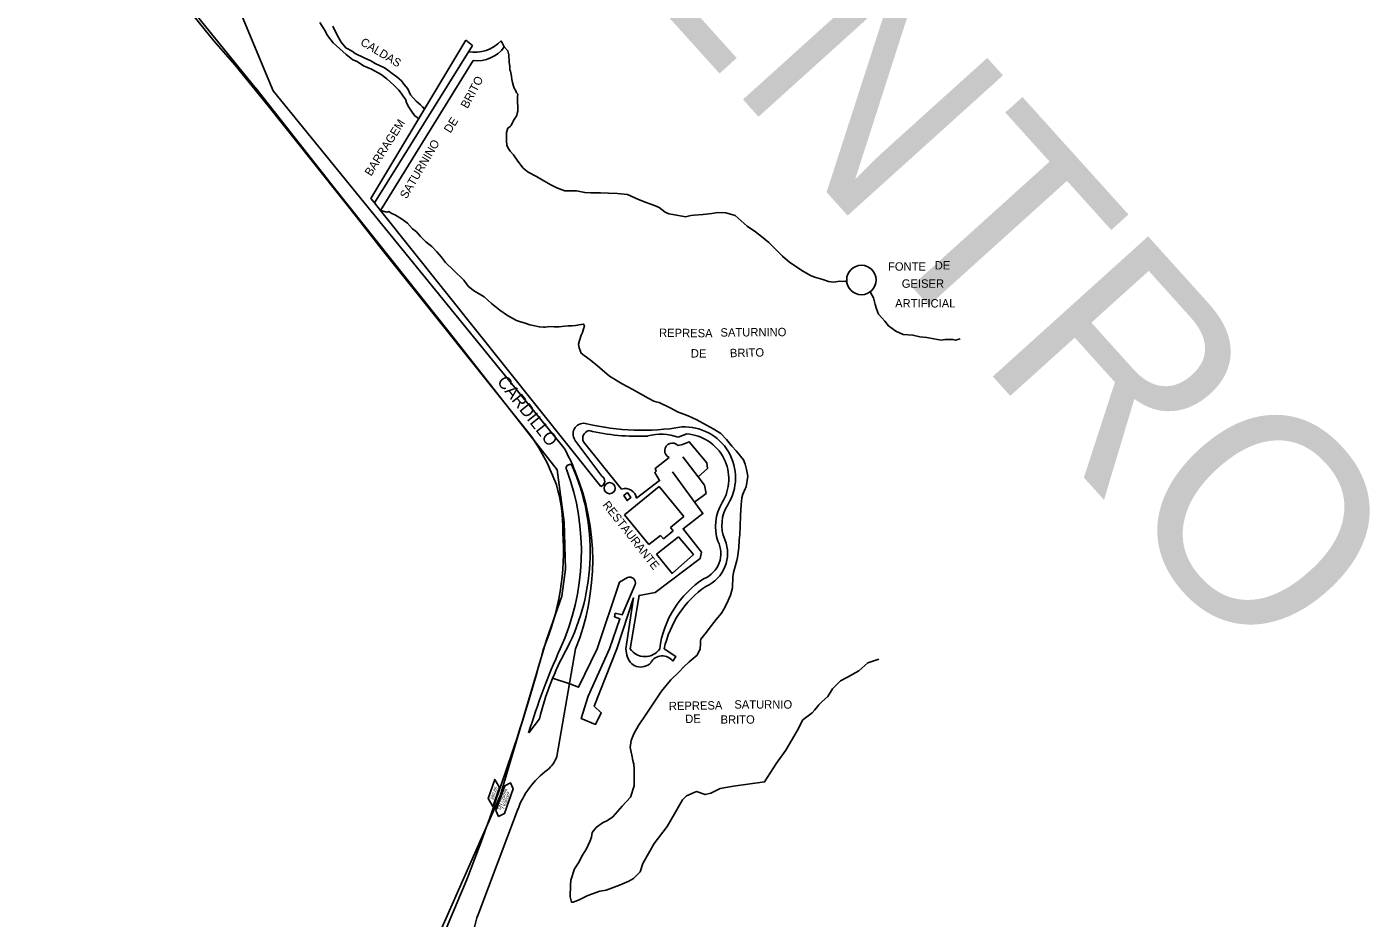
# Model space of a CAD drawing. Extents: x 325709 to 364434, y 7573432 to 7597073.
# Drawn here: x 339628 to 340271, y 7586373 to 7586799 of the extents above; entities that cross this region are included whole.
import ezdxf

# ---------------------------------------------------------------- set-up
doc = ezdxf.new("R2010")
doc.units = 0
for name, color, linetype in [('EDIFEXISTENT', 7, 'Continuous'), ('EDIFIDENTIF', 7, 'Continuous'), ('EDIFOBRAEXIS', 7, 'Continuous'), ('LIMITE_BAIRROS_MUNICIPIOS', 7, 'Continuous'), ('LOGRADOURO', 7, 'Continuous'), ('LOGRADOURO_TEXTO', 7, 'Continuous'), ('SIMBOLO', 7, 'Continuous'), ('TEXTO', 7, 'Continuous'), ('TUBO_PEAD_GN_125', 7, 'Continuous')]:
    doc.layers.add(name, color=color, linetype=linetype)

msp = doc.modelspace()

# ---------------------------------------------------------------- linework, layer by layer
at = {"layer": 'EDIFEXISTENT'}
for p, q in [((339792.51, 7586717.06), (339837.9, 7586792.71)), ((339840.97, 7586790.2), (339794.15, 7586714.93)), ((339837.9, 7586792.71), (339837.9, 7586792.71)), ((339837.9, 7586792.71), (339837.9, 7586792.71)), ((339837.9, 7586792.71), (339840.97, 7586790.2)), ((339854.7, 7586792.37), (339856.25, 7586789.42)), ((339841.37, 7586782.96), (339797.06, 7586711.32)), ((339792.51, 7586717.06), (339792.51, 7586717.06)), ((339794.15, 7586714.93), (339792.51, 7586717.06)), ((339797.06, 7586711.32), (339794.15, 7586714.93)), ((339913.76, 7586565.82), (339930.31, 7586579.38)), ((339930.31, 7586579.38), (339942.06, 7586565.04)), ((339925.28, 7586551.76), (339913.76, 7586565.82)), ((339942.06, 7586565.04), (339935.69, 7586559.82)), ((339930.97, 7586556.06), (339925.28, 7586551.76)), ((339932.34, 7586554.38), (339930.97, 7586556.06)), ((339937.01, 7586558.21), (339932.34, 7586554.38)), ((339935.69, 7586559.82), (339937.01, 7586558.21))]:
    msp.add_line(p, q, dxfattribs=at)
msp.add_circle((340026.92, 7586678.11), 7.03, dxfattribs=at)
for centre, radius, start, end in [((339841.76, 7586804.8), 17.94, 261.22228, 316.13289), ((339843.33, 7586798.82), 15.98, 262.9776, 323.96314)]:
    msp.add_arc(centre, radius, start, end, dxfattribs=at)
at = {"layer": 'EDIFOBRAEXIS'}
for p, q in [((339797.06, 7586711.32), (339902.34, 7586579.4)), ((339889.99, 7586601.64), (339902.86, 7586584.37)), ((339939.42, 7586602.99), (339943.53, 7586604.56)), ((339912.29, 7586578.21), (339894.07, 7586600.75)), ((339902.34, 7586579.4), (339902.34, 7586579.4)), ((339928.99, 7586547.03), (339939.46, 7586555.39)), ((339914.39, 7586501.91), (339914.87, 7586498.83)), ((339867.89, 7586461.75), (339873.07, 7586468.35))]:
    msp.add_line(p, q, dxfattribs=at)
for points in [[(339768.08, 7586801.11), (339770.27, 7586797.65), (339771.8, 7586794.9), (339774.4, 7586791.34), (339780.69, 7586785.81), (339783.78, 7586783.3), (339785.86, 7586782.55), (339789.02, 7586780.35), (339792.73, 7586778.81), (339797.37, 7586776.35), (339800.15, 7586774.19), (339803.45, 7586771.23), (339805.76, 7586768.73), (339806.9, 7586767.32), (339808.2, 7586765.42), (339808.98, 7586764.41), (339809.73, 7586762.37), (339810.6, 7586760.68), (339812.19, 7586758.2), (339813.46, 7586756.52), (339814.62, 7586755.65), (339815.32, 7586755.1)], [(339818.03, 7586759.75), (339817.17, 7586760.75), (339816.22, 7586761.77), (339814.1, 7586763.51), (339811.38, 7586766.59), (339810.85, 7586767.95), (339810.19, 7586769.44), (339808.27, 7586771.69), (339807.07, 7586773.3), (339804.86, 7586775.11), (339802.72, 7586776.8), (339800.64, 7586778.31), (339799.02, 7586779.4), (339794.46, 7586781.46), (339792.38, 7586782.82), (339789.31, 7586784.21), (339784.95, 7586786.27), (339783.59, 7586787.36), (339780.46, 7586788.98), (339778.3, 7586791.72), (339776.31, 7586795.14), (339774.36, 7586799.34)], [(339856.25, 7586789.42), (339858.01, 7586787.6), (339858.47, 7586785.62), (339858.51, 7586782.17), (339858.82, 7586780.14), (339858.95, 7586778.55), (339859.22, 7586777.87), (339859.67, 7586775.51), (339859.85, 7586773.81), (339860.1, 7586772.47), (339860.59, 7586770.75), (339861.01, 7586769.69), (339861.69, 7586768.41), (339862.14, 7586767.58), (339862.71, 7586766.95), (339862.53, 7586765.83), (339862.6, 7586763.34), (339862.67, 7586760.65), (339862.7, 7586758.77), (339862.42, 7586757.65), (339862.31, 7586756.71), (339860.67, 7586754.29), (339859.59, 7586751.96), (339859.04, 7586751.45), (339857.97, 7586750.56), (339857.27, 7586748.54), (339857.35, 7586746.79), (339857.23, 7586744.61), (339857.47, 7586742.5), (339858.08, 7586741.04), (339859, 7586739.63), (339860.63, 7586737.83), (339862.71, 7586734.8), (339865.26, 7586731.59), (339867.58, 7586729.55), (339871.6, 7586727.59), (339875.17, 7586725.46), (339878.48, 7586723.57), (339881.33, 7586722.14), (339885.16, 7586720.66), (339888.13, 7586720.66), (339890.83, 7586720.66), (339894.7, 7586719.84), (339897.57, 7586719.81), (339902.3, 7586719.66), (339906.09, 7586719.53), (339910.3, 7586719.4), (339915.06, 7586718.87), (339920.36, 7586716.55), (339924, 7586715.09), (339925.86, 7586714.41), (339928.11, 7586713.61), (339930.23, 7586712.76), (339933.12, 7586710.55), (339934.83, 7586709.74), (339938.63, 7586709.05), (339942.78, 7586708.31), (339945.44, 7586708.89), (339947.06, 7586709.04), (339951.22, 7586709.42), (339955.4, 7586709.9), (339958.24, 7586710.31), (339962.05, 7586710.19), (339966.57, 7586708.83), (339972.4, 7586703.82), (339976.36, 7586701.15), (339979.14, 7586698.94), (339982.7, 7586695.98), (339989.19, 7586689.41), (339992.64, 7586686.5), (339999.2, 7586682.07), (340002.89, 7586680.12), (340005.19, 7586679.35), (340008.41, 7586678.31), (340011.19, 7586677.4), (340013.77, 7586677.06), (340016.63, 7586677.47), (340018.05, 7586677.44), (340019.12, 7586677.46), (340020.07, 7586676.99)], [(339797.06, 7586711.32), (339800.17, 7586710.49), (339801, 7586710.81), (339802.21, 7586710.01), (339804.29, 7586709.14), (339807.19, 7586707.36), (339809.99, 7586705.22), (339812.4, 7586702.57), (339814.28, 7586701.08), (339816.17, 7586698.85), (339818.78, 7586696.36), (339821.67, 7586694.15), (339823.95, 7586691.6), (339826.2, 7586689.07), (339828.1, 7586686.44), (339832.03, 7586682.77), (339836.89, 7586678.01), (339839.04, 7586675.15), (339841.49, 7586673.06), (339846.62, 7586670.12), (339850.06, 7586666.81), (339854.15, 7586663.73), (339857.81, 7586661.13), (339862.12, 7586658.66), (339863.47, 7586658.2), (339866.23, 7586657.41), (339868.45, 7586656.74), (339869.98, 7586656.39), (339873.06, 7586655.7), (339874.95, 7586655.51), (339875.71, 7586655.62), (339877.99, 7586655.81), (339880.15, 7586655.65), (339882.39, 7586655.74), (339883.73, 7586655.91), (339885.15, 7586656.09), (339886.82, 7586656.15), (339888.47, 7586656.25), (339890.25, 7586656.33), (339891.26, 7586656.43), (339891.9, 7586656.64), (339893.01, 7586656.86), (339893.97, 7586657.03), (339894.2, 7586656.78), (339894.5, 7586655.85), (339894.23, 7586655.26), (339893.56, 7586653.01), (339893.05, 7586651.68), (339892.18, 7586649.15), (339891.75, 7586647.44), (339892.09, 7586645.62), (339892.94, 7586643.12), (339894.46, 7586642.08), (339897.24, 7586639.97), (339901.83, 7586636.11), (339906.55, 7586632.13), (339912.61, 7586628.48), (339917.4, 7586625.97), (339921.38, 7586623.73), (339925.02, 7586621.56), (339927.74, 7586620.23), (339928.86, 7586619.95), (339930.31, 7586619.59), (339935.82, 7586616.85), (339939.08, 7586615.07), (339944.12, 7586613.26), (339948.24, 7586611.35), (339952.86, 7586608.79), (339956.32, 7586606.87), (339959.66, 7586604.74), (339962.45, 7586601.89), (339964.97, 7586598.74), (339967.07, 7586596.39), (339970.57, 7586592.21), (339971.4, 7586590.04), (339971.97, 7586587.61), (339972.59, 7586584.32), (339971.79, 7586579.27), (339971.35, 7586578.33), (339970.3, 7586575.77), (339969.85, 7586573.96), (339969.4, 7586570.67), (339969.1, 7586565.79), (339968.99, 7586560.33), (339968.86, 7586556.54), (339968.57, 7586553.84), (339968.31, 7586550.05), (339967.68, 7586545.47), (339967.32, 7586544.09), (339965.77, 7586538.37), (339965.4, 7586536.26), (339965.27, 7586530.97), (339964.39, 7586527.5), (339962.58, 7586523.48), (339961.2, 7586520.87), (339960.04, 7586518.94), (339957.58, 7586515.85), (339954.2, 7586511.6), (339952.88, 7586509.88), (339951.52, 7586508.1), (339950.25, 7586506.56), (339950.02, 7586505.46), (339950.06, 7586504.29), (339949.78, 7586501.91)], [(340031.09, 7586672.51), (340032.72, 7586669.57), (340033.56, 7586666.44), (340034.16, 7586664.26), (340035.16, 7586661.84), (340036.62, 7586660.06), (340038.09, 7586658.49), (340039.94, 7586656.11), (340043.41, 7586653.58), (340046.87, 7586652.06), (340051.57, 7586651.79), (340054.86, 7586650.93), (340058.15, 7586650.61), (340061.56, 7586649.91), (340065, 7586649.38), (340067, 7586649.6), (340069.42, 7586649.64), (340070.66, 7586649.66), (340071.93, 7586649.4), (340074.11, 7586650)], [(339948.9, 7586583.98), (339953.3, 7586587.99), (339953.05, 7586590.68), (339944.59, 7586600.77), (339941.41, 7586599.54), (339939.29, 7586598.97)], [(339934.97, 7586593.23), (339928.4, 7586588.04), (339928.88, 7586586.78), (339928.13, 7586586.08), (339930.43, 7586582.28), (339919.43, 7586573.84)], [(339947.17, 7586571.95), (339952.72, 7586576.14), (339951.86, 7586579.99), (339948.9, 7586583.98), (339941.61, 7586593.6)], [(339916.43, 7586501.91), (339920.65, 7586527.37), (339928.32, 7586528.78), (339949.78, 7586544.98), (339950.46, 7586547.99), (339941.71, 7586559.26), (339951.18, 7586566.49), (339936.56, 7586586.4)], [(339915.09, 7586576.58), (339913.41, 7586575.18), (339914.95, 7586572.72), (339916.76, 7586574.22), (339915.09, 7586576.58)], [(339939.46, 7586555.39), (339946.62, 7586546.93), (339936.47, 7586537.86), (339928.99, 7586547.03), (339928.99, 7586547.03)], [(339900.62, 7586501.91), (339911.37, 7586533.79), (339915.17, 7586535.96)], [(339918.81, 7586532.6), (339912.61, 7586518.17), (339909.24, 7586518.84), (339908.94, 7586517.11), (339911.4, 7586516.21), (339906.56, 7586501.91)], [(339910.05, 7586501.91), (339918, 7586526.18), (339914.39, 7586501.91)], [(339879.36, 7586487.82), (339887.53, 7586485.1), (339891.75, 7586483.54), (339900.62, 7586501.91)], [(339949.78, 7586501.91), (339948.39, 7586498.86), (339944.65, 7586495.67), (339942.04, 7586493.23), (339939.59, 7586490.7), (339935.89, 7586487), (339931.4, 7586481.66), (339924.05, 7586470.7), (339920.45, 7586465.17), (339918.17, 7586461.29), (339916.95, 7586458.04), (339916.47, 7586454.72), (339917.22, 7586451.04), (339917.67, 7586448.56), (339918.23, 7586446.76), (339918.27, 7586444.4), (339918.33, 7586439.41), (339918.38, 7586436.36), (339916.49, 7586431.01), (339912.51, 7586426.62), (339908.17, 7586421.66), (339905.55, 7586419.79), (339903.23, 7586418.78), (339900.16, 7586416.44), (339898.29, 7586414.17), (339897.97, 7586411.93), (339897.07, 7586409.75), (339895.52, 7586406.31), (339893.29, 7586402.79), (339891.96, 7586400.02), (339889.78, 7586396.68), (339888.09, 7586391.36), (339887.82, 7586388.94), (339887.69, 7586383.36), (339888.34, 7586380.86), (339889.23, 7586380.77), (339892.03, 7586382.01), (339896.15, 7586383.99), (339901.97, 7586386.02), (339904.88, 7586386.62), (339911.25, 7586388.92), (339915.7, 7586390.9), (339918.04, 7586392.16), (339921.25, 7586395.39), (339922.48, 7586399.33), (339927.92, 7586408.78), (339934.1, 7586416.95), (339937.66, 7586423.01), (339941.34, 7586429.64), (339943.34, 7586431.58), (339948.09, 7586433.67), (339952.29, 7586432.26), (339954.92, 7586432.97), (339959.39, 7586435.1), (339965.86, 7586436.25), (339980.66, 7586438.3), (339986.41, 7586447.18), (339990.79, 7586453.48), (339996.26, 7586462.66), (339998.99, 7586467.89), (340003.31, 7586471.25), (340004.59, 7586472.79), (340006.58, 7586475.06), (340008.24, 7586476.62), (340010.92, 7586479.08), (340013.17, 7586482.73), (340016.93, 7586486.53), (340020.23, 7586488.32), (340025.62, 7586491.41), (340029.99, 7586495.17), (340035.28, 7586496.99)], [(339906.56, 7586501.91), (339896.38, 7586479.17), (339892.99, 7586468.5), (339899.91, 7586465.72), (339902.59, 7586471.33), (339899.25, 7586474.53), (339910.05, 7586501.91)], [(339936.81, 7586495.94), (339938.17, 7586498.25), (339932.66, 7586501.91)]]:
    msp.add_lwpolyline(points, dxfattribs=at)
msp.add_circle((339906.6, 7586578.61), 2.65, dxfattribs=at)
for centre, radius, start, end in [((339894.22, 7586604.52), 5.11, 73.21118, 214.20853), ((339922.1, 7586718.48), 112.22, 256.38813, 279.71241), ((339942.42, 7586583.59), 24.32, 328.108, 93.26946), ((339897.55, 7586602.37), 3.84, 102.17615, 204.96566), ((339919.72, 7586702.12), 98.71, 256.53693, 272.93581), ((339931.2, 7586579.63), 24.77, 70.61756, 105.02752), ((339941.93, 7586583), 21.62, 328.60275, 85.75617), ((339936.59, 7586596.51), 3.65, 42.3728, 243.70431), ((339887.5, 7586588.23), 1.72, 51.30891, 213.84702), ((339795.42, 7586548.27), 101.89, 332.93834, 23.91075), ((339781.48, 7586548.33), 111.61, 335.42253, 20.41993), ((339901.49, 7586582), 2.74, 288.1865, 59.78524), ((339913.99, 7586572.96), 5.51, 9.08964, 107.94605), ((339978.48, 7586560.42), 21.33, 147.98552, 199.55525), ((339978.16, 7586561.06), 17.93, 147.32255, 203.01892), ((339946.81, 7586547.42), 12.96, 292.41089, 26.87118), ((339945.82, 7586547.47), 17.15, 293.29235, 22.55305), ((339916.17, 7586533.4), 2.75, 343.00909, 111.48638), ((339976.77, 7586496.11), 46.61, 122.46819, 172.84914), ((339980.37, 7586491.56), 48.82, 124.66713, 167.7616), ((340188.54, 7586364.24), 335.15, 155.74592, 163.08476), ((340000.8, 7586437.88), 131.31, 150.81321, 166.58136), ((339921.46, 7586499.83), 6.67, 188.6169, 316.59357), ((339923.48, 7586506.63), 8.48, 213.81705, 326.18295), ((339931.77, 7586492.31), 6.21, 35.8459, 151.70409)]:
    msp.add_arc(centre, radius, start, end, dxfattribs=at)
at = {"layer": 'LOGRADOURO'}
for p, q in [((339745.84, 7586768.49), (339884.88, 7586597.76)), ((339890.35, 7586501.91), (339881.41, 7586450.43)), ((339862.58, 7586424.82), (339844.09, 7586375.74))]:
    msp.add_line(p, q, dxfattribs=at)
for points in [[(339575.83, 7587001.91), (339604.8, 7586940.65), (339608.85, 7586932.85), (339621.23, 7586913.4), (339639.94, 7586889.45), (339661.16, 7586862.92), (339688.1, 7586828.62), (339717.43, 7586792.4), (339727.44, 7586780.92), (339743.4, 7586761.31), (339764.54, 7586734.63), (339785.56, 7586708.2), (339797.4, 7586693.19), (339869.28, 7586603.31)], [(339680.32, 7586949.39), (339690.72, 7586907.81), (339703.09, 7586873.41), (339727.79, 7586811.58), (339745.84, 7586768.49)]]:
    msp.add_lwpolyline(points, dxfattribs=at)
for centre, radius, start, end in [((339782.4, 7586544.01), 105.19, 20.16736, 34.3144), ((339783.71, 7586543.14), 114.97, 22.237, 28.36378), ((339785.4, 7586544.01), 113.08, 338.14427, 22.15258), ((339808.35, 7586558.81), 75.89, 359.06615, 16.43246), ((339764.62, 7586548.91), 119.92, 336.92662, 4.1424), ((339065.23, 7586718.48), 838.18, 340.1718, 345.02618), ((339866.55, 7586456.24), 15.96, 310.36448, 338.62731), ((339902.07, 7586410.42), 42.04, 126.80384, 159.96437), ((339138.63, 7586670.23), 753.05, 335.73035, 341.73102), ((339888.31, 7586358.12), 47.6, 158.28133, 208.28484)]:
    msp.add_arc(centre, radius, start, end, dxfattribs=at)
at = {"layer": 'SIMBOLO'}
for points in [[(339853.9, 7586435.56), (339850.82, 7586426.46), (339848.59, 7586430.39), (339851.67, 7586439.49)], [(339852.19, 7586424.59), (339856.42, 7586436.48), (339859.21, 7586437.81), (339859.21, 7586437.81), (339860.54, 7586435.02), (339856.32, 7586423.12), (339853.52, 7586421.79), (339853.52, 7586421.79)]]:
    msp.add_lwpolyline(points, close=True, dxfattribs=at)
at = {"layer": 'TUBO_PEAD_GN_125'}
for points in [[(338915.26, 7587680.6), (339197.09, 7587428.81), (339308.81, 7587328.3), (339388.52, 7587255.32), (339496.54, 7587131.48), (339536.89, 7587087.99), (339554.95, 7587048.75), (339614.54, 7586921.04), (339737.72, 7586769.38)], [(339737.46, 7586769.67), (339775.04, 7586721.89), (339829.92, 7586653.1), (339881.59, 7586587.46), (339884.8, 7586562.34), (339885.43, 7586539.86), (339883.72, 7586527.05), (339876.45, 7586506.12), (339854.22, 7586431.62), (339810.76, 7586333.13), (339873.58, 7586260.48), (339814.07, 7586237.37), (339727, 7586065.66), (339455.3, 7585916.52), (339561.88, 7585005.03)]]:
    msp.add_lwpolyline(points, dxfattribs=at)

# ---------------------------------------------------------------- texts
at = {"layer": 'EDIFIDENTIF'}
for s, rotation, p in [('CALDAS', 328.69833, (339787.1, 7586790.67)), ('BRITO', 61.94777, (339838.69, 7586759.71)), ('DE', 57.5162, (339830.45, 7586747.98)), ('BARRAGEM', 57.5556, (339792.57, 7586727.4)), ('SATURNINO', 59.38563, (339809.49, 7586716.55)), ('REPRESA', 359.45072, (339930.21, 7586650.9)), ('SATURNINO', 0.39286, (339959.58, 7586651.03)), ('DE', 359.38883, (339945.39, 7586641.06)), ('BRITO', 1.24618, (339964.11, 7586641.18)), ('RESTAURANTE', 308.23114, (339902.95, 7586570.54)), ('REPRESA', 0.93856, (339934.92, 7586472.51)), ('DE', 1.30107, (339942.75, 7586466.4))]:
    msp.add_text(s, height=4, rotation=rotation, dxfattribs=at).set_placement(p)
for s, p in [('FONTE', (340039.64, 7586682.55)), ('DE', (340061.96, 7586683.11)), ('GEISER', (340046.21, 7586674.38)), ('ARTIFICIAL', (340043.04, 7586664.95)), ('SATURNIO', (339966.19, 7586473.3)), ('BRITO', (339959.61, 7586466.11))]:
    msp.add_text(s, height=4, dxfattribs=at).set_placement(p)
at = {"layer": 'LIMITE_BAIRROS_MUNICIPIOS'}
msp.add_text('LL JARDIM PARAISO - CENTRO', height=100, rotation=312.0533, dxfattribs=at).set_placement((338877.92, 7587975.29))
at = {"layer": 'LOGRADOURO_TEXTO'}
msp.add_text('CARDILLO', height=6, rotation=308.65113, dxfattribs=at).set_placement((339852.52, 7586629.37))
at = {"layer": 'TEXTO'}
for s, rotation, p in [('999,85', 71.2843, (339850.97, 7586429.65)), ('DN 125mm', 70.44826, (339854.36, 7586424.89)), ('7 Kgf/cm²', 70.96044, (339856.26, 7586424.89))]:
    msp.add_text(s, height=1.5, rotation=rotation, dxfattribs=at).set_placement(p)

doc.saveas('drawing.dxf')
